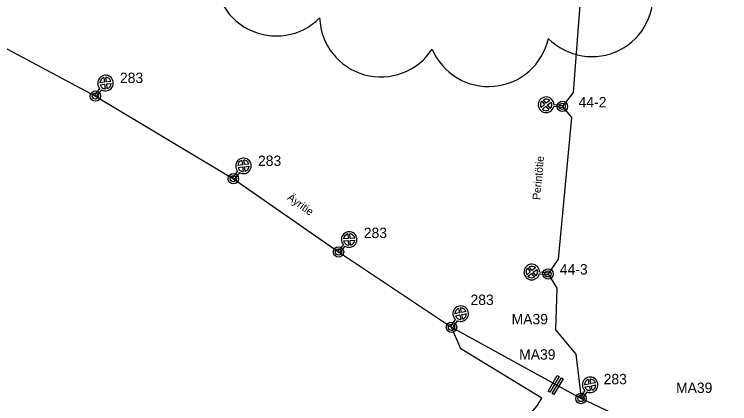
# Model space of a CAD drawing. Extents: x 25497851 to 25498523, y 6686544 to 6687372.
# Drawn here: x 25498083.9 to 25498290.2, y 6686878 to 6686990.4 of the extents above; entities that cross this region are included whole.
import ezdxf

# ---------------------------------------------------------------- set-up
doc = ezdxf.new("R2010")
doc.units = 0
for name, color, linetype in [('EL_CABLE_MAA', 7, 'Continuous'), ('KAAPELI', 7, 'Continuous'), ('KEYGWT_ANNOTATION', 7, 'Continuous'), ('Level 63', 7, 'Continuous'), ('MUU_SUUNNITELMAVIIVA', 7, 'Continuous'), ('MUU_UV-SUUNNITELMASYMBOLI', 7, 'Continuous'), ('PYLVAS', 7, 'Continuous'), ('TEKSTI_SUUNNITELMA-ALUE', 7, 'Continuous'), ('VALAISIN', 7, 'Continuous')]:
    doc.layers.add(name, color=color, linetype=linetype)

msp = doc.modelspace()

# ---------------------------------------------------------------- linework, layer by layer
at = {"layer": 'EL_CABLE_MAA'}
for points in [[(25498231.88, 6686874.15), (25498234.67, 6686877.37), (25498236.01, 6686879.59), (25498212.63, 6686893.9), (25498209.99, 6686900.07)], [(25498290.21, 6686859.18), (25498247.33, 6686879.52)]]:
    msp.add_lwpolyline(points, dxfattribs=at)
at = {"layer": 'KAAPELI'}
for p, q in [((25498067.85, 6686987.87), (25498107.28, 6686966.85)), ((25498107.28, 6686966.85), (25498147.08, 6686942.96)), ((25498147.08, 6686942.96), (25498177.4, 6686921.82)), ((25498177.4, 6686921.82), (25498209.99, 6686900.07)), ((25498209.99, 6686900.07), (25498247.33, 6686879.52))]:
    msp.add_line(p, q, dxfattribs=at)
for points in [[(25498246.09, 6687011.72), (25498248.18, 6687008.34), (25498245.03, 6686967.87), (25498241.98, 6686963.86)], [(25498241.98, 6686963.86), (25498244.55, 6686960.66), (25498240.72, 6686919.7), (25498237.84, 6686915.47)], [(25498237.84, 6686915.47), (25498240.38, 6686911.4), (25498239.99, 6686899.35), (25498245.81, 6686892.35), (25498247.33, 6686879.52)]]:
    msp.add_lwpolyline(points, dxfattribs=at)
at = {"layer": 'MUU_SUUNNITELMAVIIVA'}
for centre, start, end in [((25498159.43, 6687001.84), 170.2279, 315.2279), ((25498250.49, 6686995.87), 224.5286, 9.5286), ((25498189.6, 6686990.02), 181.9853, 326.9853), ((25498220.66, 6686987.23), 202.7536, 347.7536)]:
    msp.add_arc(centre, 17.65, start, end, dxfattribs=at)
at = {"layer": 'MUU_UV-SUUNNITELMASYMBOLI'}
for p, q in [((25498237.82, 6686881.68), (25498240.49, 6686886.2)), ((25498241.01, 6686885.89), (25498238.34, 6686881.37)), ((25498238.99, 6686880.99), (25498241.66, 6686885.51)), ((25498242.18, 6686885.2), (25498239.51, 6686880.68)), ((25498240.49, 6686886.2), (25498241.01, 6686885.89)), ((25498241.66, 6686885.51), (25498242.18, 6686885.2)), ((25498238.34, 6686881.37), (25498237.82, 6686881.68)), ((25498239.51, 6686880.68), (25498238.99, 6686880.99))]:
    msp.add_line(p, q, dxfattribs=at)
at = {"layer": 'PYLVAS'}
for centre, radius in [((25498107.28, 6686966.85), 1.5), ((25498107.28, 6686966.85), 1.5), ((25498107.28, 6686966.85), 0.9), ((25498107.28, 6686966.85), 0.9), ((25498241.98, 6686963.86), 1.5), ((25498241.98, 6686963.86), 0.9), ((25498147.08, 6686942.96), 1.5), ((25498147.08, 6686942.96), 0.9), ((25498177.4, 6686921.82), 1.5), ((25498177.4, 6686921.82), 0.9), ((25498237.84, 6686915.47), 1.5), ((25498237.84, 6686915.47), 0.9), ((25498209.99, 6686900.07), 1.5), ((25498209.99, 6686900.07), 0.9), ((25498247.33, 6686879.52), 1.5), ((25498247.33, 6686879.52), 0.9)]:
    msp.add_circle(centre, radius, dxfattribs=at)
at = {"layer": 'VALAISIN'}
for p, q in [((25498109.71, 6686972.16), (25498109.87, 6686970.85)), ((25498110.46, 6686970.92), (25498110.3, 6686972.24)), ((25498109.87, 6686970.85), (25498108.56, 6686970.69)), ((25498108.63, 6686970.09), (25498109.94, 6686970.25)), ((25498109.94, 6686970.25), (25498110.1, 6686968.94)), ((25498111.78, 6686971.08), (25498110.46, 6686970.92)), ((25498110.54, 6686970.33), (25498111.85, 6686970.49)), ((25498110.7, 6686969.02), (25498110.54, 6686970.33)), ((25498107.05, 6686967.04), (25498108.59, 6686969.02)), ((25498109.07, 6686968.65), (25498107.52, 6686966.67)), ((25498107.52, 6686966.67), (25498107.05, 6686967.04)), ((25498236, 6686965.4), (25498236.84, 6686964.37)), ((25498237.3, 6686964.75), (25498236.47, 6686965.78)), ((25498238.33, 6686965.59), (25498237.3, 6686964.75)), ((25498236.84, 6686964.37), (25498235.81, 6686963.54)), ((25498236.19, 6686963.07), (25498237.22, 6686963.91)), ((25498237.22, 6686963.91), (25498238.05, 6686962.88)), ((25498237.68, 6686964.29), (25498238.71, 6686965.12)), ((25498238.52, 6686963.26), (25498237.68, 6686964.29)), ((25498241.95, 6686963.55), (25498239.45, 6686963.8)), ((25498239.51, 6686964.4), (25498242.01, 6686964.14)), ((25498242.01, 6686964.14), (25498241.95, 6686963.55)), ((25498149.66, 6686946.96), (25498148.35, 6686946.79)), ((25498149.5, 6686948.27), (25498149.66, 6686946.96)), ((25498150.25, 6686947.03), (25498150.09, 6686948.34)), ((25498151.57, 6686947.19), (25498150.25, 6686947.03)), ((25498146.84, 6686943.14), (25498148.38, 6686945.12)), ((25498148.86, 6686944.75), (25498147.31, 6686942.77)), ((25498148.42, 6686946.2), (25498149.73, 6686946.36)), ((25498149.73, 6686946.36), (25498149.89, 6686945.05)), ((25498150.33, 6686946.43), (25498151.64, 6686946.59)), ((25498150.49, 6686945.12), (25498150.33, 6686946.43)), ((25498147.31, 6686942.77), (25498146.84, 6686943.14)), ((25498180.05, 6686927.02), (25498180.15, 6686925.7)), ((25498180.75, 6686925.75), (25498180.65, 6686927.07)), ((25498180.15, 6686925.7), (25498178.84, 6686925.59)), ((25498178.88, 6686925), (25498180.2, 6686925.1)), ((25498180.2, 6686925.1), (25498180.31, 6686923.78)), ((25498182.07, 6686925.85), (25498180.75, 6686925.75)), ((25498180.8, 6686925.15), (25498182.12, 6686925.25)), ((25498180.9, 6686923.83), (25498180.8, 6686925.15)), ((25498177.17, 6686922.01), (25498178.8, 6686923.92)), ((25498177.63, 6686921.62), (25498177.17, 6686922.01)), ((25498179.26, 6686923.53), (25498177.63, 6686921.62)), ((25498232.71, 6686916.08), (25498231.67, 6686915.26)), ((25498231.89, 6686917.12), (25498232.71, 6686916.08)), ((25498233.18, 6686916.45), (25498232.36, 6686917.49)), ((25498234.22, 6686917.26), (25498233.18, 6686916.45)), ((25498233.55, 6686915.98), (25498234.59, 6686916.79)), ((25498234.37, 6686914.94), (25498233.55, 6686915.98)), ((25498235.38, 6686916.06), (25498237.87, 6686915.76)), ((25498232.04, 6686914.79), (25498233.08, 6686915.61)), ((25498233.08, 6686915.61), (25498233.89, 6686914.57)), ((25498237.8, 6686915.16), (25498235.31, 6686915.46)), ((25498237.87, 6686915.76), (25498237.8, 6686915.16)), ((25498212.03, 6686905.53), (25498212.29, 6686904.23)), ((25498212.88, 6686904.35), (25498212.62, 6686905.65)), ((25498212.29, 6686904.23), (25498210.99, 6686903.98)), ((25498211.11, 6686903.39), (25498212.4, 6686903.65)), ((25498212.4, 6686903.65), (25498212.66, 6686902.35)), ((25498214.18, 6686904.6), (25498212.88, 6686904.35)), ((25498212.99, 6686903.76), (25498214.29, 6686904.01)), ((25498213.25, 6686902.46), (25498212.99, 6686903.76)), ((25498209.74, 6686900.23), (25498211.15, 6686902.32)), ((25498211.64, 6686901.98), (25498210.24, 6686899.9)), ((25498210.24, 6686899.9), (25498209.74, 6686900.23)), ((25498249.37, 6686884.99), (25498249.62, 6686883.69)), ((25498250.21, 6686883.81), (25498249.95, 6686885.11)), ((25498249.62, 6686883.69), (25498248.32, 6686883.44)), ((25498248.44, 6686882.85), (25498249.74, 6686883.11)), ((25498249.74, 6686883.11), (25498249.99, 6686881.81)), ((25498251.51, 6686884.07), (25498250.21, 6686883.81)), ((25498250.33, 6686883.22), (25498251.62, 6686883.48)), ((25498250.58, 6686881.92), (25498250.33, 6686883.22)), ((25498247.08, 6686879.69), (25498248.48, 6686881.77)), ((25498248.98, 6686881.44), (25498247.58, 6686879.36)), ((25498247.58, 6686879.36), (25498247.08, 6686879.69))]:
    msp.add_line(p, q, dxfattribs=at)
for centre, radius, start, end in [((25498110.2, 6686970.59), 2.25, 52.004, 224.3417), ((25498110.2, 6686970.59), 1.65, 107.4797, 176.5283), ((25498110.2, 6686970.59), 2.25, 239.6662, 52.004), ((25498110.2, 6686970.59), 1.65, 52.004, 86.5283), ((25498110.2, 6686970.59), 1.65, 17.4797, 52.004), ((25498110.2, 6686970.59), 1.65, 197.4797, 232.004), ((25498110.2, 6686970.59), 1.65, 287.4797, 356.5283), ((25498110.2, 6686970.59), 1.65, 232.004, 266.5283), ((25498237.26, 6686964.33), 2.25, 1.8054, 174.1431), ((25498237.26, 6686964.33), 1.65, 139.6188, 174.1431), ((25498237.26, 6686964.33), 1.65, 49.6188, 118.6674), ((25498237.26, 6686964.33), 2.25, 174.1431, 346.4809), ((25498237.26, 6686964.33), 1.65, 174.1431, 208.6674), ((25498237.26, 6686964.33), 1.65, 319.6188, 354.1431), ((25498237.26, 6686964.33), 1.65, 354.1431, 28.6674), ((25498237.26, 6686964.33), 1.65, 229.6188, 298.6674), ((25498149.99, 6686946.69), 2.25, 52.004, 224.3417), ((25498149.99, 6686946.69), 1.65, 107.4797, 176.5283), ((25498149.99, 6686946.69), 2.25, 239.6662, 52.004), ((25498149.99, 6686946.69), 1.65, 52.004, 86.5283), ((25498149.99, 6686946.69), 1.65, 17.4797, 52.004), ((25498149.99, 6686946.69), 1.65, 197.4797, 232.004), ((25498149.99, 6686946.69), 1.65, 232.004, 266.5283), ((25498149.99, 6686946.69), 1.65, 287.4797, 356.5283), ((25498180.48, 6686925.42), 2.25, 49.5556, 221.8933), ((25498180.48, 6686925.42), 1.65, 105.0313, 174.0799), ((25498180.48, 6686925.42), 2.25, 237.2178, 49.5556), ((25498180.48, 6686925.42), 1.65, 49.5556, 84.0799), ((25498180.48, 6686925.42), 1.65, 15.0313, 49.5556), ((25498180.48, 6686925.42), 1.65, 195.0313, 229.5556), ((25498180.48, 6686925.42), 1.65, 229.5556, 264.0799), ((25498180.48, 6686925.42), 1.65, 285.0313, 354.0799), ((25498233.13, 6686916.03), 2.25, 0.7488, 173.0866), ((25498233.13, 6686916.03), 2.25, 173.0866, 345.4243), ((25498233.13, 6686916.03), 1.65, 173.0866, 207.6109), ((25498233.13, 6686916.03), 1.65, 138.5623, 173.0866), ((25498233.13, 6686916.03), 1.65, 48.5623, 117.6109), ((25498233.13, 6686916.03), 1.65, 318.5623, 353.0866), ((25498233.13, 6686916.03), 1.65, 353.0866, 27.6109), ((25498233.13, 6686916.03), 1.65, 228.5623, 297.6109), ((25498212.64, 6686904), 2.25, 56.0415, 228.3793), ((25498212.64, 6686904), 1.65, 111.5172, 180.5658), ((25498212.64, 6686904), 2.25, 243.7038, 56.0415), ((25498212.64, 6686904), 1.65, 56.0415, 90.5658), ((25498212.64, 6686904), 1.65, 291.5172, 0.5658), ((25498212.64, 6686904), 1.65, 21.5172, 56.0415), ((25498212.64, 6686904), 1.65, 201.5172, 236.0415), ((25498212.64, 6686904), 1.65, 236.0415, 270.5658), ((25498249.97, 6686883.46), 2.25, 56.1117, 228.4495), ((25498249.97, 6686883.46), 1.65, 111.5874, 180.6361), ((25498249.97, 6686883.46), 2.25, 243.774, 56.1117), ((25498249.97, 6686883.46), 1.65, 56.1117, 90.6361), ((25498249.97, 6686883.46), 1.65, 201.5874, 236.1117), ((25498249.97, 6686883.46), 1.65, 291.5874, 0.6361), ((25498249.97, 6686883.46), 1.65, 21.5874, 56.1117), ((25498249.97, 6686883.46), 1.65, 236.1117, 270.6361)]:
    msp.add_arc(centre, radius, start, end, dxfattribs=at)

# ---------------------------------------------------------------- texts
at = {"layer": 'KEYGWT_ANNOTATION'}
for s, p in [('283', (25498114.37, 6686970.6)), ('44-2', (25498246.64, 6686963.58)), ('283', (25498154.18, 6686946.66)), ('283', (25498184.69, 6686925.84)), ('44-3', (25498241.22, 6686915.31)), ('283', (25498215.46, 6686906.52)), ('MA39', (25498227.31, 6686900.94)), ('MA39', (25498229.49, 6686890.74)), ('283', (25498253.86, 6686883.63)), ('MA39', (25498274.74, 6686881.11))]:
    msp.add_text(s, height=3, dxfattribs=at).set_placement(p)
at = {"layer": 'Level 63'}
msp.add_text('(C) KEYPRO 2000', height=0.0001, rotation=124.2, dxfattribs=at).set_placement((25498211.94, 6686902.67))
at = {"layer": 'TEKSTI_SUUNNITELMA-ALUE'}
for s, rotation, p in [('Perintötie', 84.8782, (25498235.55, 6686936.77)), ('Äyritie', 324.0004, (25498162.43, 6686937.11))]:
    msp.add_text(s, height=2.25, rotation=rotation, dxfattribs=at).set_placement(p)

doc.saveas('drawing.dxf')
